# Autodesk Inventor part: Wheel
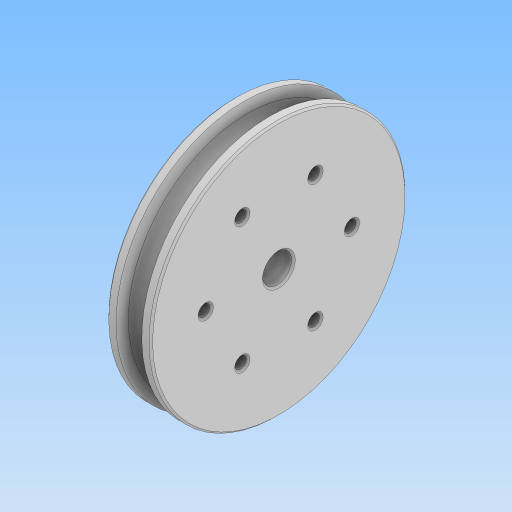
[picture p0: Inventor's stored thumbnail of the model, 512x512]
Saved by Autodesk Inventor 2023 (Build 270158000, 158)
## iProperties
Created: 2024-01
Part Number: Wheel
Material: 一般
Document SubType Name: Modeling
Designer: kumagai
Density: 1 g/cm^3
Appearance: 既定
Author: kumagai
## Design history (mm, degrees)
sketch "スケッチ1"
  geometry: L1 (0, 41.205)-(0, -2.23) reference; L2 (-9, 0)-(8.5, 0) reference; L3 (6, 35)-(6, 3.975); L4 (-6, 3.975)-(-6, 35); L5 (3.526, 35)-(2.631, 32.542); L6 (-2.631, 32.542)-(-3.526, 35); L7 (-6, 35)-(-3.526, 35); L8 (3.526, 35)-(6, 35); L9 (-6, 3.975)-(6, 3.975); L10 (-6, 3.975)-(-6.5, 3.975); L11 (-6.5, 3.975)-(-6.5, 28); L12 (-6.5, 28)-(-6, 28); A1 r 2.8 centre (0, 33.5) between (-2.631, 32.542) and (2.631, 32.542)
  constraints: 20 end point, 2 collinear, 2 point on circle, 2 point on line, 2 tangent, 1 centre point, 1 horizontal, 2 other
  dimensions: "d0" = 33.5 distance from line of L2 A1.centre; "d1" = 12 distance between parallel lines of L3 L4; "d2" = 5.6 diameter of A1; "d3" = 20 deg angle of L1 L5; "d4" = 1.5 distance from line of A1.centre L8; "d5" = 3.975 distance between parallel lines of L9 L2; "d6" = 28 distance between parallel lines of L2 L12; "d7" = 6.5 distance between parallel lines of L1 L11; "d19" = 35 distance between parallel lines of L8 L2 (derived)
revolve "回転1" sketch "スケッチ1" stored, may be unused: angle "d8" = 90 deg
sketch "スケッチ2"
  geometry: L1 (-49, 0)-(49, 0) reference; L2 (0, 49)-(0, -49) reference; C1 r 1.6 at (20, 0); 1 further point
  constraints: 1 centre point, 1 point on line
  dimensions: "d9" = 20 distance from line of C1.centre L2; "d10" = 3.2 diameter of C1
extrude "押し出し1" cut sketch "スケッチ2" extent not by distance; stored distance "d11" = 0; taper "d12" = 0 deg
pattern_circular "円形状パターン1" dims angle "d14" = 360 deg
chamfer "面取り1" distance "d16" = 0.5; stored, may be unused: second distance "d17" = 2, angle "d18" = 45 deg
node "ソリッド1"
